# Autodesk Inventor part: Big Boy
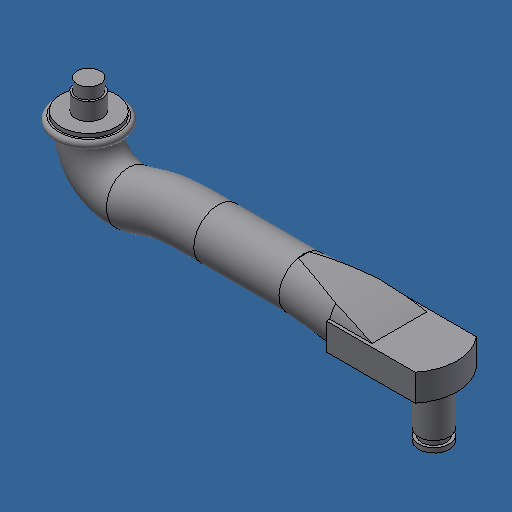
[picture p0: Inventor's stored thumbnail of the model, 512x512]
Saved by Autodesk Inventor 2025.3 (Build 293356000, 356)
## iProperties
Created: 2026-01
Part Number: Big Boy
Material: Generisch
Document SubType Name: Modeling
Mass: 14.6119 g
Surface Area: 54.148 cm^2
Volume: 14.6119 cm^3
Density: 1 g/cm^3
Appearance: Vorgabe
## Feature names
1. Sweeping2
2. Extrusion1
3. Extrusion2
4. Extrusion3
5. Extrusion4
6. Rundung1 [Fillet]
7. Umdrehung1 [Revolution]
8. Extrusion7
9. Extrusion8
10. Extrusion9
11. Extrusion10
12. Extrusion12
13. Extrusion13
## Parameters: d4 = 12.8 mm, d16 = 56 mm, d22 = 6 mm, d24 = 1 mm, d26 = 33.78514 mm, d27 = 6.75 mm, d29 = 56 mm, d30 = 0, d31 = 0, d32 = 17.5 mm, d33 = 2 mm, d34 = 0, d35 = 14.6 mm, d36 = 1 mm, d37 = 0, d38 = 7 mm, d39 = 4.5 mm, d40 = 0, d41 = 6 mm, d42 = 3 mm, d43 = 0, d44 = 1 mm, d46 = 6.75 mm, d48 = 6.4 mm, d49 = 56 mm, d50 = 7.5 mm, d51 = 7.5 mm, d53 = 90 deg, d62 = 3.25 mm, d71 = 7 mm, d72 = 96 mm, d73 = 15.5 mm, d74 = 16 mm, d75 = 0, d76 = 56 mm, d78 = 12.8 mm, d81 = 96 mm, d84 = 19.95101 mm, d85 = 15.5 mm, d86 = 16 mm, d87 = 0, d88 = 56 mm, d89 = 4.5 mm, d90 = 81 mm, d91 = 8.5 mm, d92 = 7 mm, d93 = 96 mm, d94 = 16 mm, d95 = 0, d96 = 25 mm, d97 = 83.5 mm, d99 = 25 mm, d100 = 12.5 mm, d102 = 0, d103 = 8 mm, d104 = 0, d113 = 8 mm, d115 = 8 mm, d116 = 14 mm, d117 = 0, d122 = -1.2 mm, d123 = 6.5 mm, d126 = 8 mm, d128 = 8 mm, d129 = 1.6 mm, d130 = 0
